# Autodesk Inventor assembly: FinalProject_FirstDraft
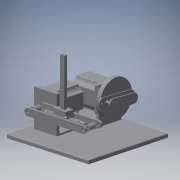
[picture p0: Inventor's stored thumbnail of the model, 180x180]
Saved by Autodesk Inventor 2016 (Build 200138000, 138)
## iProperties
Created: 2016-02
Part Number: FinalProject_FirstDraft
Document SubType Name: Assembly
Designer: Juha-Pekka
Author: Juha-Pekka
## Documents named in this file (5)
- C:\Users\Juha-Pekka\Desktop\Assignment2\FinalProject_FirstDraft.iam
- C:\Users\Juha-Pekka\Desktop\Assignment2\pohja.ipt
- C:\Users\Juha-Pekka\Desktop\Assignment2\Assembly6.iam
- C:\Users\Juha-Pekka\Desktop\Assignment2\Ohjain.iam
- C:\Users\Juha-Pekka\Desktop\Assignment2\Assembly3.iam
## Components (4 placed, 4 different names)
1. pohja:1
2. Assembly6:1 [sub-assembly]
3. Ohjain:1 [sub-assembly]
4. Assembly3:1 [sub-assembly]
